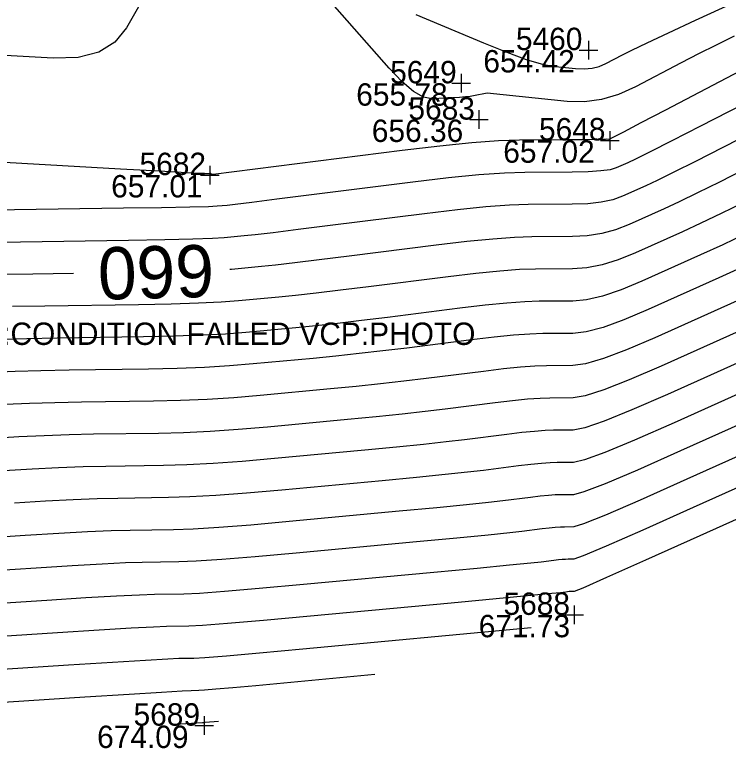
# Model space of a CAD drawing. Extents: x 2129350 to 2137777, y 657588 to 659885.
# Drawn here: x 2132684.68 to 2132723, y 657889.06 to 657928.43 of the extents above; entities that cross this region are included whole.
import ezdxf

# ---------------------------------------------------------------- set-up
doc = ezdxf.new("R2010")
doc.units = 0
for name, color, linetype in [('DT_X_Contour_Major', 7, 'Continuous'), ('DT_X_Contour_Minor', 7, 'Continuous'), ('SV_X_Shot_Marker', 7, 'Continuous'), ('SV_X_Text_Comment', 7, 'Continuous'), ('SV_X_Text_Elevation', 7, 'Continuous'), ('SV_X_Text_Name', 7, 'Continuous')]:
    doc.layers.add(name, color=color, linetype=linetype)

msp = doc.modelspace()

# ---------------------------------------------------------------- linework, layer by layer
at = {"layer": 'DT_X_Contour_Major'}
for points in [[(2132706.222, 657928.447), (2132709.856, 657926.918), (2132711.108, 657926.41), (2132712.139, 657926.033), (2132712.947, 657925.788), (2132713.534, 657925.674), (2132714.802, 657925.546), (2132715.26, 657925.526), (2132715.684, 657925.562), (2132716.073, 657925.655), (2132716.427, 657925.804), (2132717.324, 657926.277), (2132717.822, 657926.526), (2132718.642, 657926.919), (2132719.784, 657927.455), (2132721.247, 657928.136), (2132725.58, 657930.141)], [(2132723.894, 657920.142), (2132722.526, 657919.449), (2132721.347, 657918.863), (2132720.357, 657918.384), (2132719.556, 657918.013), (2132717.67, 657917.166), (2132716.949, 657916.887), (2132716.202, 657916.687), (2132715.428, 657916.565), (2132714.627, 657916.521), (2132712.455, 657916.507), (2132711.523, 657916.475), (2132710.357, 657916.389), (2132708.956, 657916.249), (2132707.321, 657916.055), (2132702.648, 657915.466), (2132701.04, 657915.266), (2132699.718, 657915.107), (2132698.683, 657914.989), (2132697.935, 657914.912), (2132696.323, 657914.761), (2132696.242, 657914.755)], [(2132687.846, 657914.542), (2132685.653, 657914.51), (2132683.818, 657914.48)], [(2132724.451, 657911.843), (2132719.395, 657909.572), (2132717.678, 657908.827), (2132716.318, 657908.294), (2132715.316, 657907.973), (2132714.67, 657907.864), (2132713.424, 657907.856), (2132712.89, 657907.838), (2132712.221, 657907.788), (2132711.418, 657907.708), (2132710.48, 657907.597), (2132707.8, 657907.259), (2132706.718, 657907.129), (2132705.485, 657906.993), (2132704.099, 657906.852), (2132702.56, 657906.704), (2132698.255, 657906.302), (2132696.678, 657906.167), (2132695.179, 657906.066), (2132693.756, 657905.997), (2132692.409, 657905.962), (2132688.921, 657905.911), (2132687.603, 657905.883), (2132686.262, 657905.837), (2132684.899, 657905.773), (2132683.515, 657905.692)], [(2132729.346, 657905.673), (2132721.121, 657901.979), (2132718.407, 657900.767), (2132716.435, 657899.9), (2132715.203, 657899.38), (2132714.713, 657899.207), (2132714.394, 657899.205), (2132714.256, 657899.2), (2132714.085, 657899.187), (2132713.879, 657899.167), (2132713.638, 657899.138), (2132712.951, 657899.052), (2132712.397, 657898.992), (2132711.252, 657898.88), (2132709.515, 657898.715), (2132707.186, 657898.496), (2132700.186, 657897.842), (2132697.816, 657897.627), (2132695.955, 657897.47), (2132694.603, 657897.373), (2132693.759, 657897.335), (2132692.19, 657897.312), (2132691.387, 657897.286), (2132690.157, 657897.224), (2132688.498, 657897.128), (2132686.411, 657896.997), (2132680.276, 657896.6)]]:
    msp.add_lwpolyline(points, dxfattribs=at)
at = {"layer": 'DT_X_Contour_Minor'}
for points in [[(2132692.047, 657930.119), (2132690.688, 657927.728), (2132690.061, 657926.953), (2132689.196, 657926.424), (2132688.094, 657926.139), (2132686.755, 657926.099), (2132682.869, 657926.319)], [(2132723.318, 657927.269), (2132722.346, 657926.797), (2132721.396, 657926.321), (2132720.468, 657925.841), (2132718.025, 657924.555), (2132717.108, 657924.144), (2132716.19, 657923.878), (2132715.27, 657923.755), (2132714.35, 657923.777), (2132710.049, 657924.212), (2132709.326, 657924.07), (2132709.139, 657924.041), (2132708.888, 657924.014), (2132708.571, 657923.99), (2132708.191, 657923.969), (2132707.09, 657923.915), (2132706.636, 657924.003), (2132706.101, 657924.306), (2132705.483, 657924.825), (2132704.784, 657925.56), (2132701.331, 657929.491)], [(2132723.612, 657925.405), (2132719.623, 657923.305), (2132718.312, 657922.617), (2132717.369, 657922.125), (2132716.794, 657921.831), (2132716.587, 657921.735), (2132716.482, 657921.746), (2132716.411, 657921.732), (2132716.275, 657921.728), (2132715.896, 657921.724), (2132715.276, 657921.719), (2132714.414, 657921.714), (2132711.793, 657921.697), (2132710.662, 657921.658), (2132709.233, 657921.551), (2132707.506, 657921.378), (2132705.482, 657921.138), (2132695.344, 657919.86), (2132695.282, 657919.856), (2132695.269, 657919.857), (2132695.258, 657919.86), (2132695.247, 657919.866), (2132695.238, 657919.874), (2132695.216, 657919.899), (2132695.208, 657919.908), (2132695.2, 657919.914), (2132695.192, 657919.917), (2132695.185, 657919.918), (2132695.165, 657919.919), (2132695.158, 657919.918), (2132695.152, 657919.915), (2132695.147, 657919.911), (2132695.131, 657919.886), (2132694.83, 657919.896), (2132693.935, 657919.942), (2132692.446, 657920.024), (2132690.363, 657920.141), (2132681.93, 657920.618)], [(2132726.087, 657924.789), (2132721.501, 657922.446), (2132719.967, 657921.664), (2132718.805, 657921.076), (2132718.015, 657920.682), (2132717.598, 657920.481), (2132716.98, 657920.203), (2132716.658, 657920.111), (2132716.155, 657920.044), (2132715.472, 657920.001), (2132714.609, 657919.983), (2132712.067, 657919.968), (2132710.976, 657919.93), (2132709.611, 657919.83), (2132707.972, 657919.666), (2132706.058, 657919.439), (2132698.768, 657918.521), (2132697.411, 657918.352), (2132696.516, 657918.243), (2132696.085, 657918.195), (2132695.55, 657918.145), (2132695.085, 657918.124), (2132694.092, 657918.1), (2132692.57, 657918.072), (2132690.519, 657918.04), (2132682.304, 657917.919)], [(2132726.939, 657923.461), (2132722.697, 657921.294), (2132721.246, 657920.557), (2132720.076, 657919.97), (2132719.186, 657919.533), (2132718.577, 657919.247), (2132717.325, 657918.685), (2132716.803, 657918.499), (2132716.178, 657918.366), (2132715.45, 657918.283), (2132714.618, 657918.252), (2132712.261, 657918.237), (2132711.25, 657918.203), (2132709.984, 657918.109), (2132708.464, 657917.957), (2132706.689, 657917.747), (2132701.618, 657917.108), (2132699.904, 657916.893), (2132698.564, 657916.729), (2132697.6, 657916.616), (2132697.01, 657916.553), (2132695.937, 657916.453), (2132695.313, 657916.416), (2132694.247, 657916.381), (2132692.739, 657916.347), (2132690.789, 657916.314), (2132684.999, 657916.23), (2132683.061, 657916.2)], [(2132723.806, 657918.341), (2132722.618, 657917.756), (2132721.528, 657917.236), (2132720.535, 657916.779), (2132718.015, 657915.647), (2132717.095, 657915.275), (2132716.225, 657915.008), (2132715.405, 657914.846), (2132714.635, 657914.789), (2132712.649, 657914.777), (2132711.796, 657914.748), (2132710.73, 657914.669), (2132709.449, 657914.541), (2132707.953, 657914.364), (2132703.679, 657913.825), (2132702.175, 657913.639), (2132700.871, 657913.484), (2132699.766, 657913.361), (2132698.86, 657913.27), (2132696.709, 657913.069), (2132695.768, 657913), (2132694.558, 657912.942), (2132693.078, 657912.897), (2132691.329, 657912.863), (2132686.307, 657912.79), (2132684.575, 657912.761)], [(2132723.889, 657916.649), (2132722.699, 657916.087), (2132721.514, 657915.545), (2132718.36, 657914.129), (2132717.241, 657913.663), (2132716.248, 657913.33), (2132715.383, 657913.128), (2132714.644, 657913.058), (2132712.842, 657913.047), (2132712.07, 657913.02), (2132711.102, 657912.949), (2132709.941, 657912.833), (2132708.585, 657912.672), (2132704.709, 657912.183), (2132703.311, 657912.011), (2132702.025, 657911.861), (2132700.849, 657911.734), (2132699.785, 657911.628), (2132697.096, 657911.377), (2132695.996, 657911.292), (2132694.713, 657911.223), (2132693.248, 657911.172), (2132691.599, 657911.138), (2132686.96, 657911.07), (2132685.332, 657911.041), (2132683.925, 657911.005)], [(2132723.87, 657914.938), (2132722.493, 657914.311), (2132718.705, 657912.61), (2132717.387, 657912.051), (2132716.272, 657911.651), (2132715.36, 657911.409), (2132714.652, 657911.326), (2132713.036, 657911.316), (2132712.343, 657911.293), (2132711.475, 657911.229), (2132710.433, 657911.124), (2132709.216, 657910.98), (2132705.739, 657910.542), (2132704.447, 657910.384), (2132703.178, 657910.239), (2132701.932, 657910.106), (2132700.71, 657909.987), (2132697.482, 657909.685), (2132696.223, 657909.583), (2132694.868, 657909.504), (2132693.417, 657909.447), (2132691.869, 657909.413), (2132687.614, 657909.351), (2132686.089, 657909.322), (2132684.704, 657909.282), (2132683.46, 657909.232)], [(2132723.472, 657913.077), (2132719.05, 657911.091), (2132717.532, 657910.439), (2132716.295, 657909.972), (2132715.338, 657909.691), (2132714.661, 657909.595), (2132713.23, 657909.586), (2132712.616, 657909.565), (2132711.848, 657909.508), (2132710.925, 657909.416), (2132709.848, 657909.288), (2132706.769, 657908.9), (2132705.583, 657908.757), (2132704.331, 657908.616), (2132703.015, 657908.479), (2132701.635, 657908.345), (2132697.868, 657907.993), (2132696.451, 657907.875), (2132695.023, 657907.785), (2132693.586, 657907.722), (2132692.139, 657907.687), (2132688.268, 657907.631), (2132686.846, 657907.602), (2132685.483, 657907.56), (2132684.179, 657907.503)], [(2132725.43, 657910.609), (2132719.741, 657908.054), (2132717.824, 657907.215), (2132716.342, 657906.615), (2132715.293, 657906.254), (2132714.678, 657906.132), (2132713.618, 657906.126), (2132713.163, 657906.11), (2132712.594, 657906.068), (2132711.91, 657906), (2132711.111, 657905.905), (2132708.83, 657905.617), (2132707.854, 657905.502), (2132706.638, 657905.371), (2132705.182, 657905.224), (2132703.485, 657905.062), (2132698.641, 657904.61), (2132696.906, 657904.459), (2132695.334, 657904.347), (2132693.925, 657904.272), (2132692.679, 657904.236), (2132689.575, 657904.191), (2132688.359, 657904.163), (2132687.041, 657904.115), (2132685.619, 657904.044), (2132684.094, 657903.953)], [(2132726.409, 657909.375), (2132720.086, 657906.535), (2132717.97, 657905.603), (2132716.365, 657904.936), (2132715.271, 657904.536), (2132714.687, 657904.401), (2132713.812, 657904.395), (2132713.436, 657904.383), (2132712.966, 657904.348), (2132712.402, 657904.291), (2132711.743, 657904.213), (2132709.86, 657903.976), (2132708.99, 657903.874), (2132707.792, 657903.748), (2132706.265, 657903.597), (2132704.41, 657903.421), (2132699.027, 657902.918), (2132697.133, 657902.751), (2132695.489, 657902.628), (2132694.094, 657902.548), (2132692.949, 657902.511), (2132690.229, 657902.471), (2132689.116, 657902.444), (2132687.82, 657902.392), (2132686.339, 657902.315), (2132684.673, 657902.214)], [(2132727.388, 657908.141), (2132720.431, 657905.016), (2132718.116, 657903.991), (2132716.388, 657903.258), (2132715.248, 657902.817), (2132714.696, 657902.669), (2132714.006, 657902.665), (2132713.71, 657902.655), (2132713.339, 657902.628), (2132712.894, 657902.583), (2132712.375, 657902.522), (2132710.89, 657902.334), (2132710.126, 657902.247), (2132708.945, 657902.125), (2132707.348, 657901.97), (2132705.335, 657901.779), (2132699.414, 657901.226), (2132697.361, 657901.043), (2132695.644, 657900.908), (2132694.264, 657900.823), (2132693.219, 657900.786), (2132690.882, 657900.751), (2132689.873, 657900.725), (2132688.599, 657900.669), (2132687.058, 657900.586), (2132685.253, 657900.475), (2132680.083, 657900.14)], [(2132728.367, 657906.907), (2132720.776, 657903.498), (2132718.262, 657902.379), (2132716.412, 657901.579), (2132715.226, 657901.099), (2132714.704, 657900.938), (2132714.2, 657900.935), (2132713.983, 657900.927), (2132713.712, 657900.908), (2132713.387, 657900.875), (2132713.007, 657900.83), (2132711.921, 657900.693), (2132711.261, 657900.62), (2132710.098, 657900.503), (2132708.431, 657900.342), (2132706.261, 657900.138), (2132699.8, 657899.534), (2132697.588, 657899.335), (2132695.799, 657899.189), (2132694.433, 657899.098), (2132693.489, 657899.06), (2132691.536, 657899.032), (2132690.63, 657899.005), (2132689.378, 657898.947), (2132687.778, 657898.857), (2132685.832, 657898.736), (2132680.179, 657898.37)], [(2132733.237, 657905.748), (2132721.466, 657900.46), (2132718.553, 657899.155), (2132716.458, 657898.222), (2132715.181, 657897.662), (2132714.722, 657897.475), (2132714.587, 657897.474), (2132714.53, 657897.472), (2132714.458, 657897.467), (2132714.371, 657897.458), (2132714.27, 657897.446), (2132713.981, 657897.41), (2132713.533, 657897.365), (2132712.405, 657897.258), (2132708.111, 657896.855), (2132700.572, 657896.15), (2132698.043, 657895.919), (2132696.11, 657895.751), (2132694.772, 657895.648), (2132694.029, 657895.609), (2132692.843, 657895.592), (2132692.144, 657895.566), (2132690.936, 657895.502), (2132689.218, 657895.399), (2132686.99, 657895.258), (2132680.372, 657894.829)], [(2132712.419, 657895.529), (2132700.157, 657894.384), (2132697.82, 657894.168), (2132696.065, 657894.013), (2132694.891, 657893.918), (2132694.299, 657893.884), (2132693.497, 657893.872), (2132692.901, 657893.847), (2132691.714, 657893.779), (2132689.937, 657893.67), (2132687.57, 657893.519), (2132680.469, 657893.059)], [(2132704.024, 657893.017), (2132697.625, 657892.419), (2132696.406, 657892.307), (2132695.49, 657892.226), (2132694.878, 657892.176), (2132694.569, 657892.158), (2132694.151, 657892.152), (2132693.677, 657892.129), (2132692.568, 657892.062), (2132690.824, 657891.952), (2132688.446, 657891.799), (2132675.867, 657890.985)], [(2132695.628, 657890.505), (2132694.916, 657890.439), (2132694.839, 657890.433), (2132694.765, 657890.431), (2132693.279, 657890.335)]]:
    msp.add_lwpolyline(points, dxfattribs=at)
at = {"layer": 'SV_X_Shot_Marker'}
for p, q in [((2132715.498, 657927.03), (2132715.498, 657926.03)), ((2132714.998, 657926.53), (2132715.998, 657926.53)), ((2132715.498, 657926.53), (2132715.498, 657926.53)), ((2132708.653, 657925.247), (2132708.653, 657924.247)), ((2132708.153, 657924.747), (2132709.153, 657924.747)), ((2132708.653, 657924.747), (2132708.653, 657924.747)), ((2132709.613, 657923.299), (2132709.613, 657922.299)), ((2132709.113, 657922.799), (2132710.113, 657922.799)), ((2132709.613, 657922.799), (2132709.613, 657922.799)), ((2132716.643, 657922.184), (2132716.643, 657921.184)), ((2132716.143, 657921.684), (2132717.143, 657921.684)), ((2132716.643, 657921.684), (2132716.643, 657921.684)), ((2132695.167, 657920.323), (2132695.167, 657919.323)), ((2132694.667, 657919.823), (2132695.667, 657919.823)), ((2132695.167, 657919.823), (2132695.167, 657919.823)), ((2132714.728, 657896.72), (2132714.728, 657895.72)), ((2132714.228, 657896.22), (2132715.228, 657896.22)), ((2132714.728, 657896.22), (2132714.728, 657896.22)), ((2132694.864, 657890.776), (2132694.864, 657889.776)), ((2132694.364, 657890.276), (2132695.364, 657890.276)), ((2132694.864, 657890.276), (2132694.864, 657890.276))]:
    msp.add_line(p, q, dxfattribs=at)

# ---------------------------------------------------------------- texts
at = {"layer": 'DT_X_Contour_Major'}
msp.add_text('660', height=2.8, rotation=181.4566, dxfattribs=at).set_placement((2132695.36, 657916.091))
at = {"layer": 'SV_X_Text_Comment'}
msp.add_text('VCP:SIZE "12""" VCP:LOCATION TOP VCP:CONDITION FAILED VCP:PHOTO', height=1.2, dxfattribs=at).set_placement((2132652.307, 657910.707))
at = {"layer": 'SV_X_Text_Elevation'}
for s, p in [('654.42', (2132709.848, 657925.33)), ('655.78', (2132703.022, 657923.547)), ('656.36', (2132703.859, 657921.599)), ('657.02', (2132710.917, 657920.484)), ('657.01', (2132689.866, 657918.623)), ('671.73', (2132709.598, 657895.02)), ('674.09', (2132689.11, 657889.076))]:
    msp.add_text(s, height=1.2, dxfattribs=at).set_placement(p)
at = {"layer": 'SV_X_Text_Name'}
for s, p in [('5460', (2132711.596, 657926.53)), ('5649', (2132704.845, 657924.747)), ('5683', (2132705.824, 657922.799)), ('5648', (2132712.835, 657921.684)), ('5682', (2132691.388, 657919.823)), ('5688', (2132710.93, 657896.22)), ('5689', (2132691.066, 657890.276))]:
    msp.add_text(s, height=1.2, dxfattribs=at).set_placement(p)

doc.saveas('drawing.dxf')
